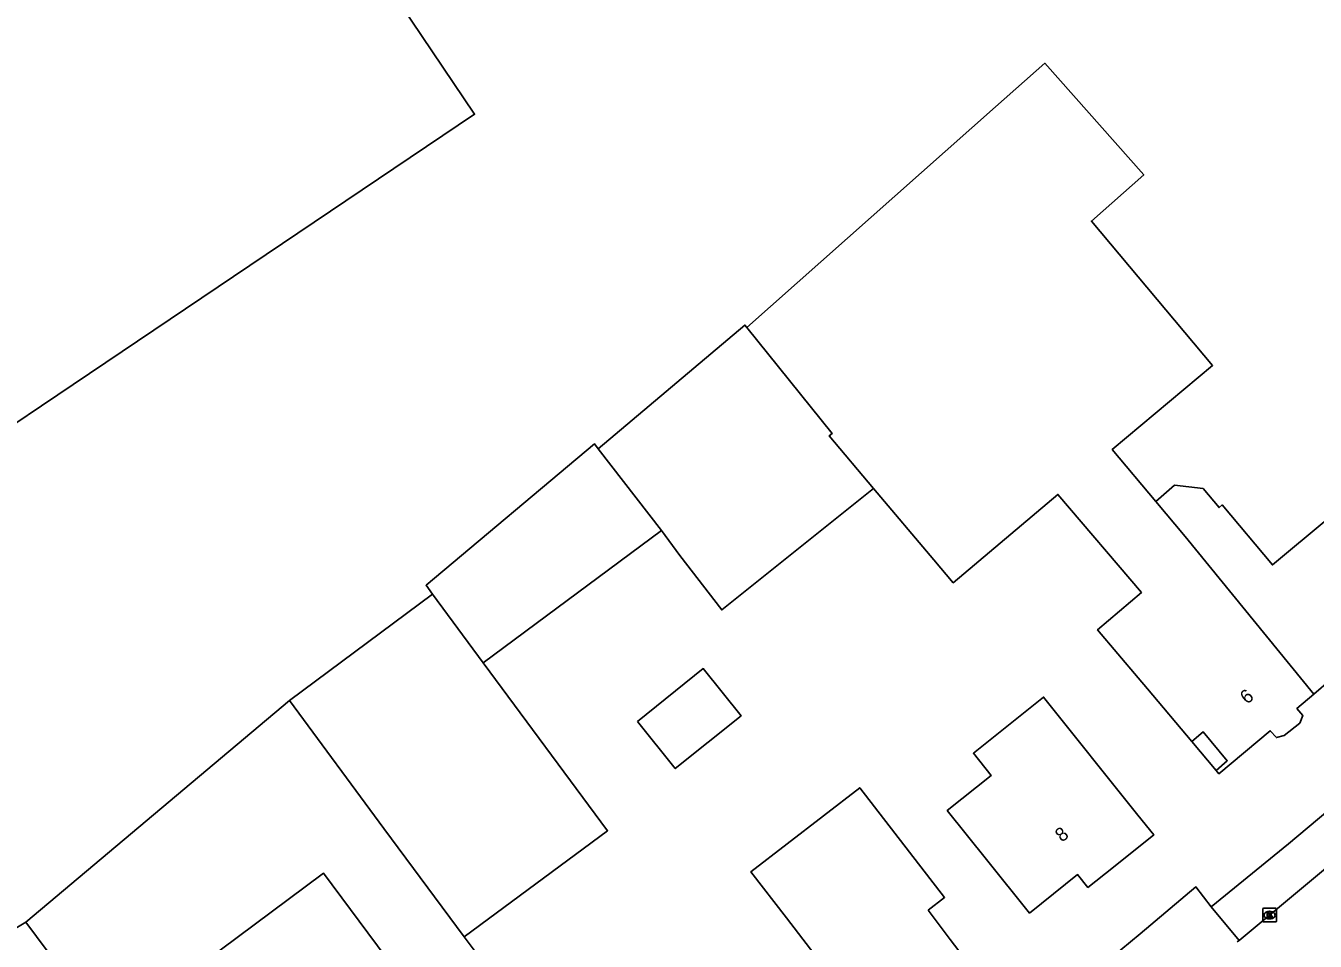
# Model space of a CAD drawing. Extents: x 156651 to 158072, y 387631 to 388990.
# Drawn here: x 157498.9 to 157592.7, y 387903.7 to 387970.3 of the extents above; entities that cross this region are included whole.
import ezdxf

# ---------------------------------------------------------------- set-up
doc = ezdxf.new("R2010")
doc.units = 0
for name, color, linetype in [('IMGEO_Kolk', 7, 'Continuous'), ('IMGEO_Pand', 7, 'Continuous'), ('IMGEO_Pand_nummerreeks', 7, 'Continuous'), ('IMGEO_Pand_overbouw', 7, 'Continuous'), ('IMGEO_Rijbaan_lokaal_open', 7, 'Continuous'), ('IMGEO_Voetpad_open', 7, 'Continuous')]:
    doc.layers.add(name, color=color, linetype=linetype)

msp = doc.modelspace()

# ---------------------------------------------------------------- linework, layer by layer
at = {"layer": 'IMGEO_Kolk'}
for p, q in [((157588.894, 387905.127), (157588.894, 387905.979)), ((157588.969, 387906.053), (157589.821, 387906.053)), ((157589.382, 387905.833), (157589.407, 387905.833)), ((157589.895, 387905.979), (157589.895, 387905.127)), ((157589.821, 387905.053), (157588.969, 387905.053)), ((157589.405, 387905.273), (157589.38, 387905.273))]:
    msp.add_line(p, q, dxfattribs=at)
for points in [[(157588.894, 387905.127), (157588.894, 387905.979)], [(157588.969, 387906.053), (157589.821, 387906.053)], [(157589.215, 387905.753), (157589.338, 387905.753), (157589.338, 387905.602), (157589.468, 387905.753), (157589.632, 387905.753), (157589.486, 387905.602), (157589.639, 387905.353), (157589.487, 387905.353), (157589.402, 387905.517), (157589.338, 387905.45), (157589.338, 387905.353), (157589.215, 387905.353), (157589.215, 387905.753)], [(157589.895, 387905.979), (157589.895, 387905.127)], [(157589.821, 387905.053), (157588.969, 387905.053)]]:
    msp.add_lwpolyline(points, dxfattribs=at)
for centre, start, end in [((157588.971, 387905.977), 91.55205, 178.44795), ((157588.971, 387905.977), 91.55205, 178.44795), ((157589.819, 387905.977), 1.55205, 88.44795), ((157589.819, 387905.977), 1.55205, 88.44795), ((157588.971, 387905.129), 181.55205, 268.44795), ((157588.971, 387905.129), 181.55205, 268.44795), ((157589.819, 387905.129), 271.55205, 358.44795), ((157589.819, 387905.129), 271.55205, 358.44795)]:
    msp.add_arc(centre, 0.0765, start, end, dxfattribs=at)
for centre, major_axis, ratio, start_param, end_param in [((157589.381, 387905.553), (-0.387, 0.002), 0.722429, 4.712389, 7.853982), ((157589.406, 387905.553), (-0.39, 0.002), 0.717154, 1.570796, 4.712389)]:
    msp.add_ellipse(centre, major_axis=major_axis, ratio=ratio, start_param=start_param, end_param=end_param, dxfattribs=at)
at = {"layer": 'IMGEO_Pand'}
for points in [[(157443.821, 388017.485), (157442.318, 388019.709), (157442.114, 388020.011), (157446.272, 388022.79), (157473.347, 388040.883), (157485.336, 388023.184), (157500, 388033.029), (157506.275, 388037.242), (157530.397, 388001.248), (157528.531, 388000), (157513.821, 387990.159), (157531.524, 387963.862), (157500, 387942.641), (157495.943, 387939.909), (157495.742, 387940.212), (157494.299, 387942.387)], [(157581.108, 387935.677), (157577.945, 387939.443), (157585.251, 387945.579), (157576.431, 387956.081), (157580.234, 387959.451), (157573.038, 387967.572), (157569.45, 387964.393), (157551.342, 387948.347)], [(157551.342, 387948.347), (157551.205, 387948.518), (157540.508, 387939.503)], [(157551.342, 387948.347), (157557.554, 387940.62), (157557.326, 387940.438), (157560.551, 387936.623)], [(157528.449, 387928.913), (157527.991, 387929.571), (157540.255, 387939.857), (157540.508, 387939.503)], [(157540.508, 387939.503), (157545.122, 387933.561)], [(157545.122, 387933.561), (157546.472, 387931.745), (157549.518, 387927.77), (157560.551, 387936.623)], [(157560.551, 387936.623), (157564.954, 387931.415), (157566.363, 387929.748), (157573.984, 387936.19), (157580.061, 387929.048), (157576.87, 387926.332), (157579.842, 387922.84), (157580.516, 387922.038), (157583.728, 387918.206), (157584.556, 387918.9), (157586.311, 387916.789), (157585.511, 387916.083), (157585.705, 387915.847), (157589.448, 387918.982), (157589.895, 387918.483), (157590.458, 387918.621), (157591.589, 387919.539), (157591.811, 387920.093), (157591.391, 387920.595), (157592.618, 387921.646)], [(157592.618, 387921.646), (157593.845, 387922.697), (157594.275, 387922.157), (157594.833, 387922.306), (157595.947, 387923.253), (157596.187, 387923.766), (157595.767, 387924.281), (157599.518, 387927.436), (157599.318, 387927.679), (157598.487, 387926.991), (157596.715, 387929.107), (157597.543, 387929.8), (157594.333, 387933.634), (157593.657, 387934.44), (157589.6, 387931.051), (157585.942, 387935.417), (157585.723, 387935.231), (157584.558, 387936.622), (157582.477, 387936.868), (157581.108, 387935.677)], [(157581.108, 387935.677), (157583.251, 387933.126), (157592.618, 387921.646)], [(157545.122, 387933.561), (157532.149, 387923.918)], [(157518.045, 387921.183), (157528.449, 387928.913)], [(157528.449, 387928.913), (157532.149, 387923.918)], [(157532.149, 387923.918), (157541.202, 387911.702), (157530.769, 387903.97)], [(157543.374, 387919.661), (157546.131, 387916.225), (157550.921, 387920.068), (157548.164, 387923.504), (157543.374, 387919.661)], [(157579.816, 387912.832), (157572.949, 387921.433), (157567.839, 387917.334), (157569.129, 387915.727), (157565.937, 387913.166), (157568.796, 387909.602), (157571.924, 387905.701), (157575.419, 387908.505), (157576.167, 387907.573), (157578.03, 387909.045), (157580.964, 387911.397), (157579.816, 387912.832)], [(157498.856, 387905.046), (157518.045, 387921.183)], [(157518.045, 387921.183), (157524.905, 387911.856), (157530.769, 387903.97)], [(157564.546, 387905.917), (157565.739, 387906.84), (157559.559, 387914.828), (157551.643, 387908.71), (157554.238, 387905.353), (157560.893, 387896.651), (157561.555, 387895.799), (157565.21, 387898.625), (157568.268, 387900.982), (157566.134, 387903.771), (157564.546, 387905.917)], [(157530.769, 387903.97), (157532.065, 387902.226), (157527.692, 387898.974), (157520.532, 387908.604), (157509.286, 387900.242), (157516.425, 387890.66), (157512.006, 387887.368)], [(157487.44, 387898.193), (157498.856, 387905.046)], [(157507.314, 387893.658), (157498.856, 387905.046)]]:
    msp.add_lwpolyline(points, dxfattribs=at)
at = {"layer": 'IMGEO_Pand_overbouw'}
msp.add_lwpolyline([(157584.556, 387918.9), (157583.728, 387918.206), (157585.511, 387916.083), (157586.311, 387916.789)], close=True, dxfattribs=at)
at = {"layer": 'IMGEO_Rijbaan_lokaal_open'}
for points in [[(157652.194, 387958.294), (157652.019, 387958.134), (157650.994, 387957.28), (157610.522, 387923.276), (157605.897, 387919.391), (157595.414, 387910.583), (157592.733, 387908.347), (157587.171, 387903.71)], [(157587.171, 387903.71), (157587.035, 387903.596)]]:
    msp.add_lwpolyline(points, dxfattribs=at)
at = {"layer": 'IMGEO_Voetpad_open'}
for points in [[(157585.134, 387906.15), (157590.77, 387910.755), (157603.872, 387921.744), (157608.52, 387925.626), (157610.764, 387927.467), (157611.111, 387927.751), (157631.486, 387944.793), (157631.753, 387944.442), (157642.563, 387953.548), (157642.274, 387953.88), (157650.669, 387960.94), (157652.642, 387962.641), (157652.9, 387962.822)], [(157585.134, 387906.15), (157584.032, 387907.609), (157579.986, 387904.199), (157577.159, 387901.855)], [(157587.171, 387903.71), (157585.134, 387906.15)]]:
    msp.add_lwpolyline(points, dxfattribs=at)

# ---------------------------------------------------------------- texts
at = {"layer": 'IMGEO_Pand_nummerreeks'}
for s, rotation, p in [('6', 39.99818, (157587.762, 387920.861)), ('8', 38.73768, (157574.279, 387910.821))]:
    msp.add_text(s, height=1, rotation=rotation, dxfattribs=at).set_placement(p)

doc.saveas('drawing.dxf')
